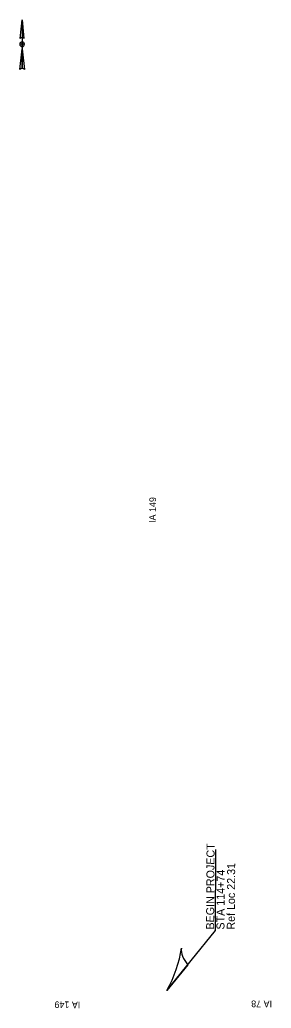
# Model space of a CAD drawing. Extents: x 23417754 to 23421386, y 6737896 to 6790956.
# Drawn here: x 23417824 to 23418578, y 6737896 to 6740861 of the extents above; entities that cross this region are included whole.
import ezdxf

# ---------------------------------------------------------------- set-up
doc = ezdxf.new("R2010")
doc.units = 0
for name, color, linetype in [('dsnCellElements', 7, 'Continuous'), ('RasterAttachment', 7, 'Continuous'), ('TextAlignmentLrg', 7, 'Continuous')]:
    doc.layers.add(name, color=color, linetype=linetype)

msp = doc.modelspace()

# ---------------------------------------------------------------- linework, layer by layer
at = {"layer": 'dsnCellElements'}
for p, q in [((23418328.1, 6738026.5), (23418265.1, 6737948.8)), ((23418328.1, 6738026.5), (23418328.1, 6738026.5)), ((23418265.9, 6737949.9), (23418265.6, 6737949.5))]:
    msp.add_line(p, q, dxfattribs=at)
msp.add_lwpolyline([(23418265.1, 6737948.8), (23418411.5, 6738129.1), (23418412.8, 6738372.2)], dxfattribs=at)
for centre, major_axis, ratio, start_param, end_param in [((23418097, 6738022.4), (153.3, 223.5), 0.670192, 4.839811, 5.363934), ((23418359, 6738046.7), (-42.7, 44.7), 0.590765, 0.44495, 1.46222)]:
    msp.add_ellipse(centre, major_axis=major_axis, ratio=ratio, start_param=start_param, end_param=end_param, dxfattribs=at)
at = {"layer": 'TextAlignmentLrg'}
for p, q in [((23417831.5, 6740861.4), (23417837.1, 6740805)), ((23417831.5, 6740861.4), (23417831.5, 6740714.9)), ((23417825.8, 6740805), (23417825.8, 6740805)), ((23417826.1, 6740805.5), (23417827.1, 6740806.7)), ((23417824.4, 6740712.1), (23417831.5, 6740774)), ((23417831.5, 6740781.1), (23417831.5, 6740781.1))]:
    msp.add_line(p, q, dxfattribs=at)
for points in [[(23417825.8, 6740805), (23417831.5, 6740861.4), (23417831.5, 6740807.8)], [(23417831.5, 6740781.1), (23417831.5, 6740788.1), (23417824.4, 6740788.1)], [(23417838.5, 6740788.1), (23417831.5, 6740788.1), (23417831.5, 6740795.2)], [(23417831.5, 6740714.9), (23417831.5, 6740774), (23417838.5, 6740712.1)]]:
    msp.add_lwpolyline(points, dxfattribs=at)
for centre, radius, start, end in [((23417831.5, 6740788.1), 7.04, 90, 180), ((23417831.5, 6740788.1), 7.04, 180, 270), ((23417831.5, 6740800.8), 7.04, 90.0204, 143.1257), ((23417831.5, 6740800.8), 7.04, 36.8481, 90.0218), ((23417831.5, 6740788.1), 7.04, 0, 90), ((23417831.5, 6740788.1), 7.04, 270, 360), ((23417831.5, 6740704.7), 10.2, 89.9894, 133.619), ((23417831.5, 6740704.7), 10.2, 46.4021, 90.0006)]:
    msp.add_arc(centre, radius, start, end, dxfattribs=at)

# ---------------------------------------------------------------- texts
at = {"layer": 'dsnCellElements'}
for s, height, p in [('BEGIN PROJECT', 24.007, (23418407.2, 6738132)), ('Ref Loc 22.31', 24.007, (23418469.3, 6738131.7)), ('STA 114+74', 24.01, (23418438.2, 6738131.9))]:
    msp.add_text(s, height=height, rotation=89.6836, dxfattribs=at).set_placement(p)
at = {"layer": 'RasterAttachment'}
for s, rotation, p in [('IA 149', 89.5786, (23418232.4, 6739351.9)), ('IA 149', 179.5786, (23418006, 6737915.9)), ('IA 78', 179.5786, (23418581, 6737918.6))]:
    msp.add_text(s, height=20, rotation=rotation, dxfattribs=at).set_placement(p)

doc.saveas('drawing.dxf')
